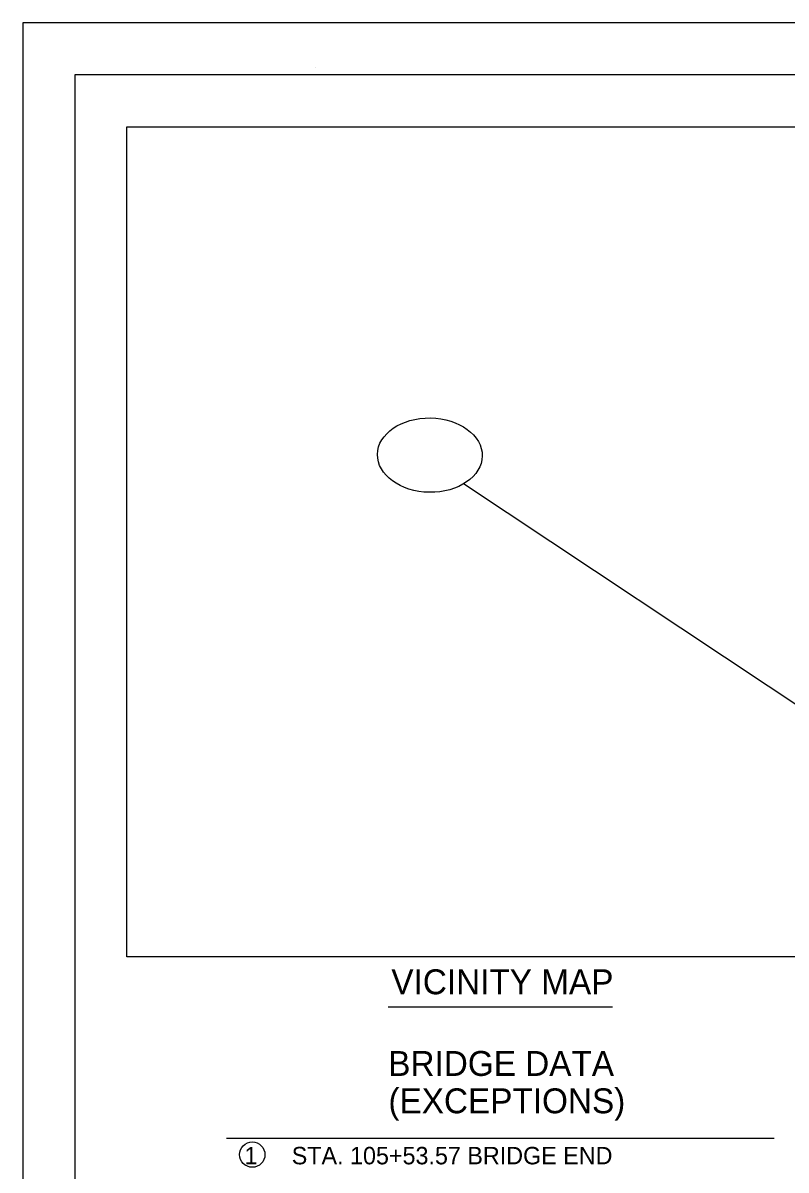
# Model space of a CAD drawing. Extents: x -0.25 to 1.92, y 0 to 0.95.
# Drawn here: x 0 to 0.3064, y 0.4561 to 0.9167 of the extents above; entities that cross this region are included whole.
import ezdxf

# ---------------------------------------------------------------- set-up
doc = ezdxf.new("R2010")
doc.units = 0
for name, color, linetype in [('Default', 7, 'Continuous'), ('DSN_DRFT_DNC', 7, 'Continuous'), ('DSN_DRFT_Guideline-No-Plot', 7, 'Continuous'), ('SHET_Annotations', 7, 'Continuous'), ('SHET_Border-Lines', 7, 'Continuous'), ('SHET_Border-Text', 7, 'Continuous')]:
    doc.layers.add(name, color=color, linetype=linetype)

msp = doc.modelspace()

# ---------------------------------------------------------------- linework, layer by layer
at = {"layer": 'Default'}
msp.add_line((0.36732, 0.60506), (0.17682, 0.73155), dxfattribs=at)
msp.add_ellipse((0.16338, 0.74314), major_axis=(-0.02104, 0.00031), ratio=0.709841, dxfattribs=at)
at = {"layer": 'DSN_DRFT_DNC'}
msp.add_lwpolyline([(0.04167, 0.875), (0.34167, 0.875), (0.34167, 0.54167), (0.04167, 0.54167)], close=True, dxfattribs=at)
at = {"layer": 'DSN_DRFT_Guideline-No-Plot'}
msp.add_lwpolyline([(0, 0), (1.41667, 0), (1.41667, 0.91667), (0, 0.91667)], close=True, dxfattribs=at)
at = {"layer": 'SHET_Annotations'}
msp.add_circle((0.09208, 0.46227), 0.00509, dxfattribs=at)
at = {"layer": 'SHET_Border-Lines'}
msp.add_line((0.11759, 0.89881), (0.11759, 0.89881), dxfattribs=at)
msp.add_line((0.11759, 0.89881), (0.11759, 0.89881), dxfattribs=at)
msp.add_lwpolyline([(0.02083, 0.02083), (1.39583, 0.02083), (1.39583, 0.89583), (0.02083, 0.89583)], close=True, dxfattribs=at)
at = {"layer": 'SHET_Border-Text'}
for p, q in [((0.14667, 0.52167), (0.23667, 0.52167)), ((0.08167, 0.46888), (0.30167, 0.46888))]:
    msp.add_line(p, q, dxfattribs=at)

# ---------------------------------------------------------------- texts
at = {"layer": 'SHET_Annotations'}
for s, height, p in [('VICINITY MAP', 0.01, (0.14791, 0.52667)), ('1', 0.007, (0.08896, 0.45838)), ('STA. 105+53.57 BRIDGE END', 0.007, (0.10792, 0.45838))]:
    msp.add_text(s, height=height, dxfattribs=at).set_placement(p)
at = {"layer": 'SHET_Border-Text'}
for s, p in [('BRIDGE DATA', (0.14667, 0.49388)), ('(EXCEPTIONS)', (0.14674, 0.47888))]:
    msp.add_text(s, height=0.01, dxfattribs=at).set_placement(p)

doc.saveas('drawing.dxf')
